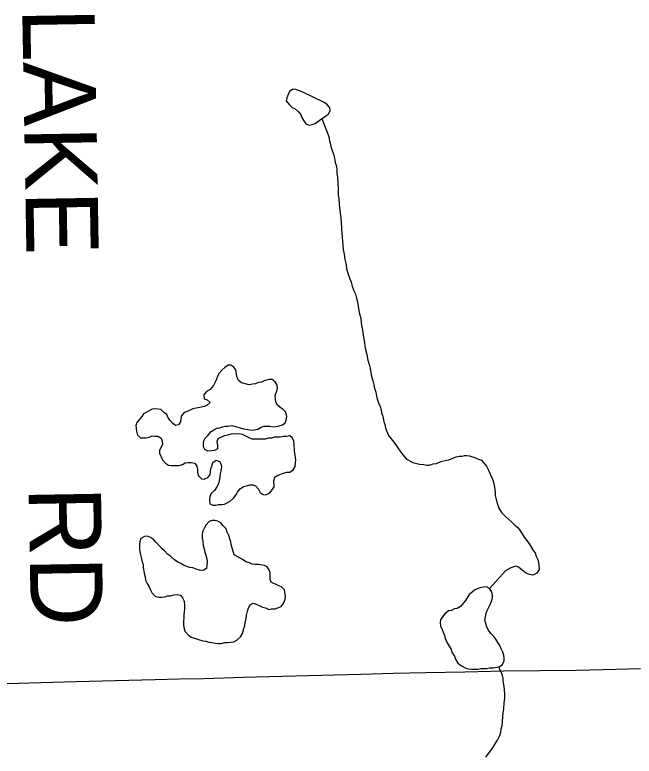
# Model space of a CAD drawing. Extents: x 103424 to 290657, y 38711 to 110967.
# Drawn here: x 141824 to 144407, y 63924 to 67015 of the extents above; entities that cross this region are included whole.
import ezdxf

# ---------------------------------------------------------------- set-up
doc = ezdxf.new("R2010")
doc.units = 0
for name, color, linetype in [('GM_X_County_Road_Text', 7, 'Continuous'), ('GM_X_Minor_Lake', 7, 'Continuous'), ('GM_X_Minor_River', 7, 'Continuous'), ('GM_X_Township_Road', 7, 'Continuous')]:
    doc.layers.add(name, color=color, linetype=linetype)

msp = doc.modelspace()

# ---------------------------------------------------------------- linework, layer by layer
at = {"layer": 'GM_X_Minor_Lake'}
for points in [[(143024.4, 66692.9), (143007.6, 66700), (142995.5, 66703.9), (142983.4, 66705.8), (142969.4, 66695.5), (142963.5, 66683.3), (142957.6, 66669.1), (142955.7, 66657), (142968, 66641), (142980.3, 66629.1), (142992.4, 66623.2), (143006.7, 66611.3), (143016.9, 66599.3), (143021.1, 66587.3), (143029.4, 66573.2), (143037.6, 66561.2), (143051.8, 66555.4)], [(143051.8, 66555.4), (143063.8, 66557.6), (143075.9, 66561.8), (143103.8, 66582.3), (143117.9, 66590.6), (143131.8, 66602.8), (143139.7, 66615), (143137.6, 66627.1), (143125.3, 66643.1), (143111.1, 66651), (143024.4, 66692.9)], [(142970.7, 65108), (142984.7, 65118.3), (142992.5, 65132.5), (142994.4, 65146.6), (142996.3, 65158.7), (142994.1, 65170.8), (142991.9, 65186.9), (142989.7, 65199), (142989.4, 65223.2), (142987.2, 65237.3), (142981, 65253.4), (142968.8, 65259.2), (142956.7, 65257.1), (142944.6, 65256.9), (142930.6, 65254.7), (142906.4, 65254.4), (142894.3, 65250.2), (142882.2, 65250), (142868.2, 65245.8), (142854, 65245.6), (142839.9, 65245.4), (142813.7, 65245.1), (142801.6, 65251), (142787.3, 65258.9), (142773.2, 65264.7), (142761, 65268.6), (142748.9, 65266.4), (142736.8, 65268.3), (142724.7, 65266.1), (142710.7, 65261.9), (142698.6, 65259.7), (142686.6, 65255.5), (142670.5, 65247.2), (142666.7, 65235.1), (142668.8, 65221), (142669.1, 65204.9), (142657, 65198.6), (142645, 65196.5), (142628.8, 65196.2), (142616.7, 65202.1), (142610.5, 65214.2), (142610.3, 65226.3), (142612.2, 65238.4), (142618.1, 65250.6), (142630, 65262.8), (142642, 65277.1), (142654, 65285.3), (142666, 65291.5), (142678, 65293.7), (142690.1, 65297.9), (142702.2, 65300.1), (142714.2, 65300.3), (142726.3, 65302.4), (142740.5, 65300.6), (142776.9, 65289), (142813.3, 65283.4), (142837.4, 65287.8), (142851.4, 65296), (142863.5, 65300.2), (142875.6, 65300.4), (142887.7, 65300.5), (142899.8, 65296.7), (142911.9, 65298.8), (142926, 65301), (142940, 65305.3), (142952, 65313.5), (142955.9, 65325.7), (142957.7, 65339.8), (142953.5, 65357.9), (142943.3, 65369.9), (142931.1, 65377.8), (142918.8, 65387.7), (142912.6, 65399.7), (142910.4, 65415.8), (142910.3, 65429.9), (142916.1, 65446.1), (142920, 65458.3), (142917.8, 65470.4), (142909.6, 65484.4), (142897.4, 65494.3), (142885.3, 65494.2), (142867.2, 65489.9), (142853.2, 65483.6), (142841.1, 65481.5), (142827, 65477.2), (142814.9, 65475.1), (142800.9, 65472.9), (142768.5, 65480.5), (142756.3, 65490.4), (142750, 65506.5), (142745.7, 65534.7)], [(142745.7, 65534.7), (142737.4, 65546.7), (142725.3, 65554.6), (142713.2, 65554.4), (142699.2, 65544.1), (142687.2, 65533.9), (142675.3, 65519.6), (142669.4, 65507.4), (142665.5, 65495.3), (142659.6, 65483.1), (142651.7, 65468.9), (142637.8, 65452.6), (142623.8, 65444.3), (142611.8, 65430), (142614.1, 65413.9), (142626.2, 65410), (142638.5, 65398.1)], [(142638.5, 65398.1), (142626.5, 65387.9), (142614.5, 65381.6), (142602.4, 65379.5), (142566.2, 65372.9), (142542.1, 65360.5), (142530.1, 65356.3), (142518.2, 65342), (142514.4, 65317.8), (142506.5, 65305.6), (142494.4, 65303.4), (142482.2, 65311.3), (142472, 65323.3), (142463.8, 65335.3), (142457.6, 65349.3), (142445.4, 65357.2), (142433.1, 65369.2), (142408.9, 65372.9), (142396.8, 65370.7), (142360.8, 65352.1), (142352.9, 65339.9), (142333, 65315.4), (142329.1, 65303.2), (142329.3, 65291.1), (142331.4, 65279.1), (142335.6, 65263), (142347.9, 65251), (142372.1, 65251.4), (142384.2, 65253.5), (142396.2, 65259.7), (142408.3, 65257.9), (142420.4, 65258.1), (142434.6, 65250.2), (142438.8, 65238.1), (142439, 65224), (142427.2, 65199.6), (142427.3, 65187.5), (142439.8, 65159.5), (142452, 65145.5), (142464.2, 65137.6), (142476.3, 65135.7), (142508.6, 65136.2), (142522.6, 65140.4), (142534.7, 65146.6), (142546.7, 65148.8), (142558.8, 65148.9), (142575, 65145.1), (142583.2, 65133.1), (142585.4, 65121), (142585.6, 65106.9), (142589.8, 65092.9), (142602, 65080.9), (142614.1, 65079.1), (142628.2, 65085.3), (142638.1, 65097.5), (142641.8, 65121.8), (142645.7, 65133.9), (142649.6, 65148.1), (142663.6, 65158.4), (142677.7, 65152.5), (142683.9, 65140.5), (142686.1, 65128.4), (142682.3, 65114.3), (142680.4, 65102.1), (142678.6, 65086), (142676.7, 65073.8), (142672.8, 65059.7), (142666.9, 65047.5), (142657.1, 65031.2), (142643.1, 65018.9), (142637.2, 65006.7), (142635.3, 64992.6), (142637.6, 64976.5)], [(142637.6, 64976.5), (142649.7, 64970.6), (142661.8, 64970.8), (142673.9, 64972.9), (142686, 64973.1), (142698.1, 64975.3), (142722.1, 64987.7), (142736.1, 65000), (142746, 65012.2), (142751.9, 65024.4), (142763.8, 65038.7), (142777.8, 65049), (142789.9, 65051.1), (142804, 65055.3), (142816, 65055.5), (142828.2, 65051.6), (142840.5, 65037.7), (142846.7, 65023.6), (142858.9, 65015.7), (142871, 65013.9), (142887, 65022.2), (142897, 65034.4), (142904.9, 65046.6), (142904.5, 65072.8), (142908.4, 65087), (142920.4, 65095.2), (142944.5, 65103.6), (142958.6, 65107.8), (142970.7, 65108)], [(142739.1, 64763.5), (142726.3, 64806.2), (142724.2, 64818.3), (142720, 64830.3), (142715.8, 64844.4), (142709.6, 64858.4), (142705.4, 64872.5), (142693.1, 64884.4), (142682.9, 64896.4), (142670.7, 64904.3), (142658.6, 64906.2), (142646.5, 64906), (142634.4, 64901.8), (142620.5, 64887.5), (142606.7, 64859.1), (142604.9, 64845), (142605, 64832.8), (142607.2, 64820.8), (142609.5, 64800.6), (142613.7, 64788.6), (142615.8, 64774.5), (142620, 64762.4), (142624.2, 64746.4), (142626.4, 64734.3), (142622.7, 64706), (142608.7, 64697.7), (142594.6, 64699.6), (142580.4, 64703.4), (142566.2, 64709.3), (142554.1, 64711.1), (142529.8, 64718.9), (142515.6, 64726.8), (142503.4, 64732.7), (142489.2, 64742.5)], [(142489.2, 64742.5), (142472.9, 64758.5), (142460.7, 64766.4), (142448.4, 64780.3), (142436.2, 64790.3), (142423.9, 64804.2), (142411.7, 64816.2), (142401.5, 64828.1), (142389.3, 64836), (142377.1, 64841.9), (142365, 64839.7), (142349, 64831.5), (142345.1, 64819.3), (142343.3, 64803.2), (142343.5, 64789), (142345.6, 64777), (142347.8, 64762.9), (142352, 64746.8), (142354.2, 64734.7), (142358.4, 64722.7), (142358.5, 64710.6), (142362.9, 64686.4), (142367.1, 64672.4), (142369.3, 64658.3), (142375.5, 64644.2), (142383.7, 64630.2), (142389.9, 64618.2), (142396.1, 64604.2), (142410.4, 64590.2), (142424.6, 64586.4), (142436.7, 64586.5), (142448.7, 64588.7), (142460.8, 64592.9), (142472.9, 64593.1), (142489, 64597.3), (142501.1, 64597.5), (142515.2, 64595.6), (142523.4, 64583.7), (142529.6, 64569.6), (142531.9, 64551.5), (142532, 64539.4), (142530.2, 64525.2), (142528.3, 64513.1), (142528.5, 64501), (142526.6, 64486.9), (142526.8, 64472.7), (142528.9, 64460.7), (142533.2, 64444.6)], [(142533.2, 64444.6), (142547.5, 64428.6), (142559.7, 64420.7), (142608.3, 64405.2), (142620.4, 64403.4), (142632.5, 64399.5), (142644.6, 64397.6), (142660.8, 64395.8), (142672.9, 64394), (142685, 64394.2), (142699.1, 64398.4), (142711.2, 64398.5), (142723.3, 64398.7), (142737.3, 64400.9), (142749.4, 64407.1), (142765.3, 64421.4), (142773.2, 64435.7), (142779, 64455.9), (142782.9, 64468.1), (142784.8, 64482.2), (142788.6, 64496.4), (142790.4, 64512.6), (142794.3, 64528.7), (142798.1, 64542.9), (142806, 64555.1), (142818.1, 64561.3), (142830.2, 64557.4), (142842.4, 64551.6), (142856.6, 64545.7), (142868.7, 64541.8), (142882.9, 64536), (142895, 64538.1), (142909.1, 64538.3), (142921.1, 64542.5), (142935.2, 64548.7), (142945.1, 64563), (142950.9, 64579.2), (142952.8, 64591.3), (142948.4, 64617.5), (142936.2, 64629.5), (142922, 64635.3), (142893.6, 64649.1), (142889.4, 64661.1), (142889.1, 64689.3), (142884.9, 64701.4), (142876.7, 64713.4), (142864.5, 64719.3), (142840.3, 64723), (142826.2, 64722.8), (142814, 64724.7), (142801.9, 64730.6), (142787.7, 64734.4), (142775.5, 64742.3), (142739.1, 64763.5)], [(143672, 64312.4), (143686.2, 64300.5), (143704.5, 64290.6), (143716.6, 64288.8), (143728.7, 64286.9), (143754.9, 64287.3), (143767, 64289.5), (143791.2, 64289.8), (143803.3, 64292), (143819.4, 64292.2), (143843.5, 64296.5), (143857.5, 64306.8), (143865.4, 64321), (143865.3, 64333.1), (143863.1, 64345.2), (143858.9, 64357.2), (143852.7, 64371.3), (143846.5, 64385.3), (143838.3, 64397.3), (143830.1, 64411.3), (143821.8, 64423.3), (143809.6, 64435.3), (143799.3, 64449.2), (143793.1, 64461.3), (143788.9, 64477.3), (143784.7, 64491.4), (143786.6, 64505.5), (143790.4, 64519.7), (143794.3, 64531.9), (143806.1, 64556.2), (143812, 64570.4), (143815.8, 64584.6), (143815.7, 64596.7), (143811.5, 64610.8), (143803.3, 64622.8), (143791.1, 64630.7), (143779, 64628.5), (143764.9, 64626.3), (143752.9, 64622.1), (143740.8, 64615.9), (143722.9, 64601.5), (143722.7, 64601.4)], [(143722.7, 64601.4), (143718.9, 64597.4), (143703.1, 64573), (143683.2, 64548.6), (143669.2, 64540.3), (143657.1, 64538.1), (143645.1, 64531.9), (143633, 64529.7), (143617, 64517.4), (143607.1, 64505.2), (143599.2, 64493), (143597.3, 64480.9), (143599.5, 64466.8), (143605.7, 64452.7), (143609.9, 64440.7), (143616.1, 64426.6), (143618.3, 64414.6), (143626.6, 64396.5), (143643.1, 64368.5), (143647.3, 64354.4), (143657.5, 64340.5), (143661.7, 64328.4), (143672, 64312.4)]]:
    msp.add_lwpolyline(points, dxfattribs=at)
at = {"layer": 'GM_X_Minor_River'}
for points in [[(143103.8, 66582.3), (143135.2, 66503.9), (143135.3, 66495.8), (143139.7, 66479.7), (143142, 66465.7), (143146.3, 66453.6), (143152.8, 66433.6), (143157.2, 66417.5), (143159.6, 66401.4), (143163.9, 66387.4), (143166.2, 66373.3), (143166.6, 66355.2), (143169, 66337), (143171.5, 66314.9), (143172.1, 66288.6), (143172.6, 66264.4), (143175, 66246.3), (143177.8, 66210), (143182.5, 66177.8), (143185.1, 66151.6), (143185.8, 66121.3), (143191.2, 66054.8), (143193.6, 66036.7), (143198.1, 66016.6), (143200.5, 65996.5), (143205.1, 65974.4), (143207.5, 65956.3), (143214, 65934.2), (143220.5, 65914.1), (143226.9, 65900.1), (143231.2, 65884.1), (143237.7, 65864), (143244.1, 65850), (143248.5, 65834), (143252.9, 65817.9), (143255.3, 65799.8), (143259.9, 65773.7), (143266.4, 65749.6), (143268.9, 65731.5), (143271.3, 65713.3), (143273.5, 65703.3), (143275.9, 65687.2), (143282.8, 65647), (143285.3, 65624.8), (143291.9, 65598.7), (143296.4, 65574.6), (143303, 65552.5), (143305.2, 65542.4), (143309.9, 65514.3), (143314.2, 65498.2), (143318.6, 65484.2), (143320.8, 65474.1), (143323.1, 65462.1), (143329.6, 65442), (143334.1, 65417.9), (143340.6, 65397.8), (143347, 65381.8), (143351.4, 65367.8), (143353.7, 65355.7), (143357.9, 65345.7), (143360.2, 65333.7), (143362.5, 65319.6), (143366.8, 65307.6), (143369.2, 65291.5), (143381.9, 65261.4), (143398.6, 65239.6), (143413.1, 65221.7), (143421.4, 65209.8), (143433.9, 65191.9), (143442.3, 65180), (143456.8, 65162.1), (143483.4, 65148.6), (143511.8, 65141.1), (143530.1, 65139.5), (143542.2, 65137.7), (143552.3, 65138), (143568.4, 65142.3), (143582.5, 65144.7), (143600.5, 65153.1), (143624.7, 65157.7), (143634.7, 65159.9), (143650.8, 65166.3), (143664.8, 65172.7), (143678.9, 65175), (143689, 65175.2), (143699, 65177.5), (143709.1, 65177.7), (143719.3, 65175.9), (143733.5, 65172.2), (143745.7, 65168.4), (143758, 65162.6), (143770.2, 65158.8), (143790.9, 65133), (143799.4, 65117.1), (143807.9, 65097.1), (143816.3, 65079.1), (143820.6, 65067.1), (143825.1, 65045), (143827.6, 65024.8), (143827.9, 65010.7), (143832.4, 64988.6)], [(143832.4, 64988.6), (143836.7, 64974.5), (143843.2, 64958.5), (143853.6, 64940.6), (143870.2, 64922.8), (143882.5, 64912.9), (143894.9, 64901.1), (143909.3, 64887.3), (143921.7, 64877.4), (143932.1, 64863.5), (143940.4, 64851.6), (143948.8, 64837.7), (143959.2, 64823.7), (143969.6, 64809.8), (143975.9, 64797.9), (143986.4, 64781.9), (143994.7, 64772), (143999, 64758), (144005.4, 64744), (144007.7, 64731.9), (144009.9, 64719.9), (144010.3, 64701.7), (144000.5, 64687.3), (143984.5, 64678.9), (143966.3, 64682.6), (143954, 64688.4), (143939.6, 64700.2), (143925.2, 64711.9), (143913, 64715.7), (143892.9, 64709.2), (143871, 64696.6), (143859.1, 64684.3), (143803.3, 64622.8)], [(143864.5, 64145.3), (143868.1, 64165.6), (143867.7, 64183.7), (143865.1, 64213.9), (143860.6, 64236.1), (143860.3, 64248.2), (143858, 64260.2), (143853.7, 64272.3), (143847.4, 64284.2), (143843.5, 64296.5)], [(143788.5, 63919.5), (143804.2, 63940.1), (143818, 63958.5), (143827.7, 63974.9), (143837.5, 63991.2), (143847.2, 64009.6), (143850.9, 64023.9), (143852.7, 64038), (143856.4, 64052.2), (143858.1, 64068.4), (143859.7, 64088.7), (143861.3, 64104.8), (143863, 64123), (143864.5, 64145.3)]]:
    msp.add_lwpolyline(points, dxfattribs=at)
at = {"layer": 'GM_X_Township_Road'}
msp.add_lwpolyline([(141789.1, 64227.5), (141934.1, 64231.2), (142079.2, 64234.9), (142244.2, 64239.1), (142409.2, 64243.3), (142510.8, 64245.9), (142612.4, 64248.5), (142777.4, 64252.8), (142939.9, 64257), (143102.3, 64261.2), (143267.3, 64265.7), (143402.5, 64269.4), (143537.8, 64273.2), (143700.4, 64276.3), (143863, 64279.4), (144015, 64280.7), (144167.1, 64282), (144332, 64286.4), (144434.2, 64289)], dxfattribs=at)

# ---------------------------------------------------------------- texts
at = {"layer": 'GM_X_County_Road_Text'}
for s, rotation, p in [('LAKE', 270.9882, (141854.4, 67043.1)), ('RD', 270.9891, (141880.9, 65046.3))]:
    msp.add_text(s, height=301.87, rotation=rotation, dxfattribs=at).set_placement(p)

doc.saveas('drawing.dxf')
